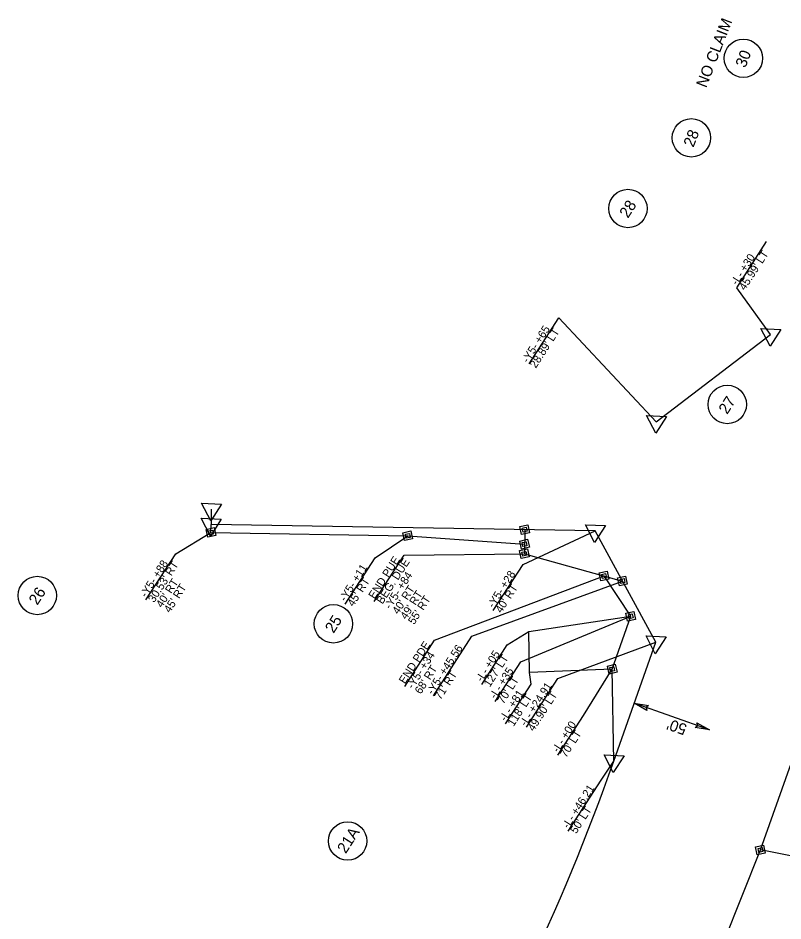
# Model space of a CAD drawing. Extents: x 1975689 to 1978251, y 778490 to 782347.
# Drawn here: x 1976889 to 1977366, y 780568 to 781132 of the extents above; entities that cross this region are included whole.
import ezdxf

# ---------------------------------------------------------------- set-up
doc = ezdxf.new("R2010")
doc.units = 0
for name, color, linetype in [('Prop Easement Construction', 7, 'Continuous'), ('Prop Easement Construction Station Offsets', 7, 'Continuous'), ('Prop Easement Permanent Drainage', 7, 'Continuous'), ('Prop Easement Permanent Drainage Station Offsets', 7, 'Continuous'), ('Prop Easement Permanent Drainage Utility', 7, 'Continuous'), ('Prop Easement Permanent Drainage Utility Station Offsets', 7, 'Continuous'), ('Prop Easement Permanent Utility', 7, 'Continuous'), ('Prop Easement Permanent Utility Station Offsets', 7, 'Continuous'), ('Prop Parcel Number CELL', 7, 'Continuous'), ('Prop ROW Marker CELL', 7, 'Continuous'), ('Prop ROW Permanent Easement CELL', 7, 'Continuous'), ('Prop ROW RW Lines', 7, 'Continuous'), ('Prop ROW Station Offsets', 7, 'Continuous'), ('Prop ROW Text', 7, 'Continuous'), ('Prop Terminator CELL', 7, 'Continuous')]:
    doc.layers.add(name, color=color, linetype=linetype)

msp = doc.modelspace()

# ---------------------------------------------------------------- linework, layer by layer
at = {"layer": 'Prop Easement Construction'}
for p, q in [((1977207.52, 780748.86), (1977271.24, 780758.26)), ((1977208.05, 780723.24), (1977207.52, 780748.86)), ((1977259.63, 780725.24), (1977208.05, 780723.24))]:
    msp.add_line(p, q, dxfattribs=at)
at = {"layer": 'Prop Easement Construction Station Offsets'}
for p, q in [((1977194.09, 780740.44), (1977207.52, 780748.86)), ((1977178.11, 780715.69), (1977194.09, 780740.44)), ((1977208.96, 780715.86), (1977208.05, 780723.24)), ((1977192.98, 780691.11), (1977208.96, 780715.86))]:
    msp.add_line(p, q, dxfattribs=at)
at = {"layer": 'Prop Easement Permanent Drainage'}
for p, q in [((1977271.24, 780758.26), (1977254.54, 780783.51)), ((1977259.63, 780725.24), (1977271.24, 780758.26)), ((1977260.65, 780667.86), (1977259.63, 780725.24))]:
    msp.add_line(p, q, dxfattribs=at)
at = {"layer": 'Prop Easement Permanent Drainage Station Offsets'}
for p, q in [((1977148.66, 780743.28), (1977254.54, 780783.51)), ((1977202.59, 780729.87), (1977271.24, 780758.26)), ((1977130.06, 780714.47), (1977148.66, 780743.28)), ((1977186.61, 780705.12), (1977202.59, 780729.87)), ((1977241.74, 780696.35), (1977259.63, 780725.24)), ((1977225.77, 780671.6), (1977241.74, 780696.35))]:
    msp.add_line(p, q, dxfattribs=at)
at = {"layer": 'Prop Easement Permanent Drainage Utility'}
for p, q in [((1977205.02, 780812.34), (1977204.77, 780797.35)), ((1977204.77, 780797.35), (1977266.04, 780780.31))]:
    msp.add_line(p, q, dxfattribs=at)
at = {"layer": 'Prop Easement Permanent Drainage Utility Station Offsets'}
for p, q in [((1977111.04, 780767.62), (1977129.64, 780796.43)), ((1977129.64, 780796.43), (1977204.77, 780797.35)), ((1977171.99, 780745.87), (1977266.04, 780780.31)), ((1977147.96, 780708.64), (1977171.99, 780745.87))]:
    msp.add_line(p, q, dxfattribs=at)
at = {"layer": 'Prop Easement Permanent Utility'}
for p, q in [((1977008.96, 780810.64), (1977009.05, 780815.64)), ((1977008.96, 780810.64), (1977131.94, 780808.57)), ((1977131.94, 780808.57), (1977204.87, 780803.34)), ((1977352.24, 780612.29), (1977384, 780702.12)), ((1977313.74, 780515.73), (1977352.24, 780612.29))]:
    msp.add_line(p, q, dxfattribs=at)
at = {"layer": 'Prop Easement Permanent Utility Station Offsets'}
for p, q in [((1976987, 780797.28), (1977008.96, 780810.64)), ((1977111.48, 780794.76), (1977131.94, 780808.57)), ((1976968.4, 780768.47), (1976987, 780797.28)), ((1977092.88, 780765.94), (1977111.48, 780794.76)), ((1977397.14, 780603.32), (1977352.24, 780612.29))]:
    msp.add_line(p, q, dxfattribs=at)
at = {"layer": 'Prop Parcel Number CELL'}
for p, q in [((1977341.58, 781106.91), (1977341.58, 781106.91)), ((1977309.09, 781057.21), (1977309.09, 781057.21)), ((1977269.47, 781013.06), (1977269.47, 781013.06)), ((1977331.51, 780890.62), (1977331.51, 780890.62)), ((1976900.51, 780771.27), (1976900.51, 780771.27)), ((1977085.5, 780753.58), (1977085.5, 780753.58)), ((1977094.37, 780617.87), (1977094.37, 780617.87))]:
    msp.add_line(p, q, dxfattribs=at)
for centre in [(1977341.58, 781106.91), (1977309.09, 781057.21), (1977269.47, 781013.06), (1977331.51, 780890.62), (1976900.51, 780771.27), (1977085.5, 780753.58), (1977094.37, 780617.87)]:
    msp.add_circle(centre, 12, dxfattribs=at)
at = {"layer": 'Prop ROW Marker CELL'}
for p, q in [((1977358.58, 780934.25), (1977358.58, 780934.25)), ((1977287.17, 780879.86), (1977287.17, 780879.86)), ((1977009.2, 780825.11), (1977009.2, 780825.11)), ((1977009.05, 780815.64), (1977009.05, 780815.64)), ((1977008.96, 780810.64), (1977008.96, 780810.64)), ((1977205.02, 780812.34), (1977205.02, 780812.34)), ((1977249.01, 780811.6), (1977249.01, 780811.6)), ((1977249.01, 780811.6), (1977249.01, 780811.6)), ((1977249.01, 780811.6), (1977249.01, 780811.6)), ((1977131.94, 780808.57), (1977131.94, 780808.57)), ((1977204.87, 780803.34), (1977204.87, 780803.34)), ((1977204.76, 780797.35), (1977204.76, 780797.35)), ((1977254.54, 780783.51), (1977254.54, 780783.51)), ((1977266.04, 780780.31), (1977266.04, 780780.31)), ((1977271.24, 780758.26), (1977271.24, 780758.26)), ((1977286.85, 780742.07), (1977286.85, 780742.07)), ((1977259.63, 780725.24), (1977259.63, 780725.24)), ((1977260.65, 780667.86), (1977260.65, 780667.86)), ((1977352.24, 780612.29), (1977352.24, 780612.29))]:
    msp.add_line(p, q, dxfattribs=at)
for points in [[(1977358.22, 780927.05), (1977352.53, 780938.15), (1977364.99, 780937.55)], [(1977286.8, 780872.66), (1977281.12, 780883.77), (1977293.58, 780883.16)], [(1977008.84, 780817.91), (1977003.15, 780829.01), (1977015.61, 780828.41)], [(1977008.69, 780808.44), (1977002.99, 780819.54), (1977015.46, 780818.95)], [(1977248.65, 780804.4), (1977242.96, 780815.51), (1977255.43, 780814.9)], [(1977248.65, 780804.4), (1977242.96, 780815.51), (1977255.43, 780814.9)], [(1977248.65, 780804.4), (1977242.96, 780815.51), (1977255.43, 780814.9)], [(1977286.49, 780734.87), (1977280.81, 780745.98), (1977293.27, 780745.37)], [(1977260.29, 780660.66), (1977254.6, 780671.76), (1977267.07, 780671.16)]]:
    msp.add_lwpolyline(points, close=True, dxfattribs=at)
at = {"layer": 'Prop ROW Permanent Easement CELL'}
for points in [[(1977201.99, 780814.29), (1977206.96, 780815.37), (1977208.04, 780810.4), (1977203.07, 780809.32)], [(1977005.93, 780812.59), (1977010.91, 780813.67), (1977011.99, 780808.7), (1977007.01, 780807.61)], [(1977007.45, 780811.62), (1977009.93, 780812.16), (1977010.47, 780809.67), (1977007.99, 780809.13)], [(1977128.92, 780810.52), (1977133.89, 780811.6), (1977134.97, 780806.63), (1977130, 780805.54)], [(1977130.43, 780809.55), (1977132.92, 780810.09), (1977133.46, 780807.6), (1977130.97, 780807.06)], [(1977203.5, 780813.32), (1977205.99, 780813.86), (1977206.53, 780811.37), (1977204.04, 780810.83)], [(1977201.84, 780805.29), (1977206.81, 780806.37), (1977207.89, 780801.4), (1977202.92, 780800.32)], [(1977203.35, 780804.32), (1977205.84, 780804.86), (1977206.38, 780802.37), (1977203.89, 780801.83)], [(1977201.74, 780799.29), (1977206.71, 780800.37), (1977207.79, 780795.4), (1977202.82, 780794.32)], [(1977203.25, 780798.32), (1977205.74, 780798.86), (1977206.28, 780796.37), (1977203.79, 780795.83)], [(1977251.51, 780785.46), (1977256.49, 780786.54), (1977257.57, 780781.56), (1977252.59, 780780.48)], [(1977253.03, 780784.48), (1977255.51, 780785.02), (1977256.05, 780782.54), (1977253.57, 780781.99)], [(1977263.01, 780782.26), (1977267.99, 780783.34), (1977269.07, 780778.36), (1977264.1, 780777.28)], [(1977264.53, 780781.28), (1977267.02, 780781.83), (1977267.56, 780779.34), (1977265.07, 780778.8)], [(1977268.21, 780760.2), (1977273.19, 780761.28), (1977274.27, 780756.31), (1977269.29, 780755.23)], [(1977269.73, 780759.23), (1977272.21, 780759.77), (1977272.76, 780757.28), (1977270.27, 780756.74)], [(1977256.6, 780727.19), (1977261.58, 780728.27), (1977262.66, 780723.29), (1977257.68, 780722.21)], [(1977258.12, 780726.21), (1977260.6, 780726.75), (1977261.14, 780724.27), (1977258.66, 780723.72)], [(1977349.21, 780614.24), (1977354.19, 780615.32), (1977355.27, 780610.34), (1977350.29, 780609.26)], [(1977350.73, 780613.26), (1977353.21, 780613.8), (1977353.75, 780611.32), (1977351.27, 780610.78)]]:
    msp.add_lwpolyline(points, close=True, dxfattribs=at)
at = {"layer": 'Prop ROW RW Lines'}
for p, q in [((1977287.17, 780879.86), (1977358.58, 780934.25)), ((1977009.2, 780825.11), (1977009.05, 780815.64)), ((1977249.01, 780811.6), (1977009.05, 780815.64)), ((1977286.85, 780742.07), (1977249.01, 780811.6)), ((1977260.65, 780667.86), (1977286.85, 780742.07))]:
    msp.add_line(p, q, dxfattribs=at)
msp.add_arc((1975987.1, 781115.69), 1350, 315.73946, 340.62647, dxfattribs=at)
at = {"layer": 'Prop ROW Station Offsets'}
for p, q in [((1977337.48, 780963.56), (1977356.08, 780992.37)), ((1977358.58, 780934.25), (1977337.48, 780963.56)), ((1977207.7, 780915.96), (1977226.3, 780944.77)), ((1977287.17, 780879.86), (1977226.3, 780944.77)), ((1977203.95, 780790.69), (1977249.01, 780811.6)), ((1977185.35, 780761.88), (1977203.95, 780790.69)), ((1977225.72, 780719.5), (1977286.85, 780742.07)), ((1977206.01, 780688.97), (1977225.72, 780719.5)), ((1977252.65, 780655.89), (1977260.65, 780667.86)), ((1977232.1, 780624.05), (1977252.65, 780655.89))]:
    msp.add_line(p, q, dxfattribs=at)
at = {"layer": 'Prop ROW Text'}
msp.add_line((1977320.51, 780687.35), (1977273.34, 780703.93), dxfattribs=at)
at = {"layer": 'Prop Terminator CELL'}
for points in [[(1977281.31, 780699.49), (1977273.34, 780703.93), (1977282.41, 780702.44), (1977280.79, 780701.31)], [(1977312.53, 780691.79), (1977320.51, 780687.35), (1977311.44, 780688.84), (1977313.05, 780689.97)]]:
    msp.add_lwpolyline(points, close=True, dxfattribs=at)

# ---------------------------------------------------------------- texts
at = {"layer": 'Prop Easement Construction Station Offsets'}
for s, p in [('-L- +05', (1977178.22, 780716.86)), ("127' LT", (1977183.17, 780713.66)), ('-L- +81', (1977193.08, 780692.28)), ("118' LT", (1977198.03, 780689.08))]:
    msp.add_text(s, height=5, rotation=57.1585, dxfattribs=at).set_placement(p)
at = {"layer": 'Prop Easement Permanent Drainage Station Offsets'}
for s, p in [('END PDE', (1977130.17, 780715.64)), ('-Y5- +34', (1977135.12, 780712.44)), ("68' RT", (1977140.07, 780709.24)), ('-L- +35', (1977186.72, 780706.29)), ("70' LT", (1977191.67, 780703.09)), ('-L- +00', (1977225.87, 780672.77)), ("70' LT", (1977230.82, 780669.57))]:
    msp.add_text(s, height=5, rotation=57.1585, dxfattribs=at).set_placement(p)
at = {"layer": 'Prop Easement Permanent Drainage Utility Station Offsets'}
for s, p in [('END PUE', (1977111.17, 780768.71)), ('BEG. DUE', (1977116.12, 780765.51)), ('-Y5- +84', (1977121.07, 780762.32)), ("40' RT", (1977126.02, 780759.12)), ("49' RT", (1977130.97, 780755.92)), ("55' RT", (1977135.92, 780752.73)), ('-Y5- +45.56', (1977147.48, 780708.9)), ("71' RT", (1977152.43, 780705.7))]:
    msp.add_text(s, height=5, rotation=57.1585, dxfattribs=at).set_placement(p)
at = {"layer": 'Prop Easement Permanent Utility Station Offsets'}
for s, p in [('-Y5- +88', (1976968.51, 780769.64)), ("30.53' RT", (1976973.46, 780766.44)), ('-Y5- +11', (1977092.99, 780767.11)), ("40' RT", (1976978.41, 780763.25)), ("45' RT", (1977097.94, 780763.92)), ("45' RT", (1976983.36, 780760.05))]:
    msp.add_text(s, height=5, rotation=57.1585, dxfattribs=at).set_placement(p)
at = {"layer": 'Prop Parcel Number CELL'}
for s, rotation, p in [('NO CLAIM', 68.7457, (1977318.35, 781088.05)), ('30', 68.7457, (1977342.86, 781100.59)), ('28', 68.7457, (1977310.37, 781050.9)), ('28', 57.2884, (1977269.5, 781006.6)), ('27', 57.2884, (1977331.45, 780884.03)), ('26', 57.2884, (1976900.55, 780764.82)), ('25', 57.2884, (1977085.6, 780747.24)), ('21A', 57.2884, (1977093.2, 780609.56))]:
    msp.add_text(s, height=7, rotation=rotation, dxfattribs=at).set_placement(p)
at = {"layer": 'Prop ROW Station Offsets'}
for s, p in [('-L- +30', (1977337.59, 780964.73)), ("45.99' LT", (1977342.54, 780961.53)), ('-Y5- +65', (1977206.98, 780916.12)), ("28.89' LT", (1977211.93, 780912.92)), ('-Y5- +28', (1977185.46, 780763.04)), ("40' RT", (1977190.41, 780759.85)), ('-L- +24.91', (1977205.65, 780689.2)), ("49.90' LT", (1977210.61, 780686)), ('-L- +46.21', (1977232.2, 780625.22)), ("50' LT", (1977237.16, 780622.03))]:
    msp.add_text(s, height=5, rotation=57.1585, dxfattribs=at).set_placement(p)
at = {"layer": 'Prop ROW Text'}
msp.add_text("50'", height=7, rotation=160.6265, dxfattribs=at).set_placement((1977306.89, 780690.42))

doc.saveas('drawing.dxf')
